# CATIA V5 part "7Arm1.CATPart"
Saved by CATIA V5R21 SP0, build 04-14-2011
Part number: Arm1
Bounding box of the stored display mesh (mm): x -25 to 11, y 73.29 to 108.29, z 135.805 to 383.286
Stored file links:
  C:\Users\水心\Desktop\Arm_Detailed_Design_Assembly_Manu\7Arm1.CATPart
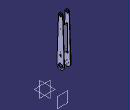
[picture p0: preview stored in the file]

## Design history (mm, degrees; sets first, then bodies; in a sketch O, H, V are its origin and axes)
Body1 (main body)
  DatumSurface1
  DatumSurface2
  Sketch1 on face of DatumSurface1, origin (-22, 0, 0), H (0, -1, 0), V (0, 0, 1)
    arc A1 centre (-90.79, 153.3046) radius 17.5 from (-108.2798, 153.9012) to (-73.3002, 153.9012) ccw
    point P1 (-90.79, 153.3046)
    arc A2 centre (-90.79, 373.3046) radius 10 from (-80.7958, 373.6456) to (-100.7842, 373.6456) ccw
    point P2 (-90.79, 373.3046)
    line L1 (-80.7958, 373.6456) -> (-73.3002, 153.9012)
    line L2 (-100.7842, 373.6456) -> (-108.2798, 153.9012)
    axis line L3 (-90.79, 373.3046) -> (-90.79, 153.3046)
    construction circle A3 centre (-90.79, 153.3046) radius 12.25
    circle A4 centre (-90.79, 161.8046) radius 1.25
    point P7 (-90.79, 161.8046)
    circle A5 centre (-90.79, 313.3046) radius 1.25
    point P8 (-90.79, 313.3046)
    circle A6 centre (-90.79, 213.3046) radius 1.25
    point P9 (-90.79, 213.3046)
    circle A7 centre (-90.79, 373.3046) radius 6.9
    circle A8 centre (-99.29, 153.3046) radius 1.25
    circle A9 centre (-90.79, 144.8046) radius 1.25
    circle A10 centre (-82.29, 153.3046) radius 1.25
    line L4 (-94.79, 203.3046) -> (-86.79, 203.3046)
    line L5 (-86.79, 203.3046) -> (-86.79, 193.3046)
    line L6 (-86.79, 193.3046) -> (-94.79, 193.3046)
    line L7 (-94.79, 193.3046) -> (-94.79, 203.3046)
    reference projected line E1 (-86.79, 203.3046) -> (-94.79, 203.3046) from edge [end face of Pad2 | face of Pocket3 from Sketch5.L1]
    reference projected line E2 (-86.79, 203.3046) -> (-86.79, 193.3046) from edge [face of Pocket3 from Sketch5.L4 | end face of Pad2]
    reference projected line E3 (-94.79, 193.3046) -> (-86.79, 193.3046) from edge [end face of Pad2 | face of Pocket3 from Sketch5.L3]
    reference projected line E4 (-94.79, 193.3046) -> (-94.79, 203.3046) from edge [face of Pocket3 from Sketch5.L2 | end face of Pad2]
    radius A1 = 17.5
    radius A2 = 10
    distance P2 P1 = 220
    radius A3 = 12.25
    radius A4 = 1.25
    distance P7 P1 = 8.5
    radius A5 = 1.25
    distance P8 P2 = 60
    radius A6 = 1.25
    distance P9 P8 = 100
    radius A7 = 6.9
    tangency: L1 A2, L1 A1, L2 A2, L2 A1
    vertical: L3 V, L5 V, L7 V
    coincidence: P7 L3, P8 L3, P9 L3, L4 E1, L5 E2, L6 E3, L7 E4
    horizontal: L4 H, L6 H
  Pad1: profile Sketch1, direction (-1, 0, 0), length 3
  Plane1: type Offset, RefPlane zx-plane, Offset 90
  Sketch2 on Plane1, origin (0, 90, 0), H (-1, 0, 0), V (0, 0, 1)
    circle A1 centre (23.5, 373.6456) radius 0.75
    point P1 (23.5, 373.6456)
    reference projected line E1 (22, 383.3046) -> (22, 373.6456) from edge [start face of Pad1 | face of Pad1 from Sketch1.A2]
    reference projected line E2 (22, 373.6456) -> (25, 373.6456) from edge [face of Pad1 from Sketch1.L2 | face of Pad1 from Sketch1.A2]
    radius A1 = 0.75
    distance P1 E1 = 1.5
    coincidence: P1 E2
  Pocket1: profile Sketch2, direction (0, -1, 0), length 20, mirrored extent
Body2
  DatumSurface3
  DatumCurve1
  DatumSurface4 to DatumSurface6
  Sketch3 on DatumSurface6, origin (11, 0, 0), H (0, -1, 0), V (0, 0, 1)
    arc A1 centre (-90.79, 153.3046) radius 17.5 from (-108.2798, 153.9012) to (-73.3002, 153.9012) ccw
    point P1 (-90.79, 153.3046)
    arc A2 centre (-90.79, 373.3046) radius 10 from (-80.7958, 373.6456) to (-100.7842, 373.6456) ccw
    point P2 (-90.79, 373.3046)
    axis line L1 (-90.79, 431.4654) -> (-90.79, 58.352)
    line L2 (-100.7842, 373.6456) -> (-108.2798, 153.9012)
    line L3 (-80.7958, 373.6456) -> (-73.3002, 153.9012)
    reference projected arc E1 centre (-90.79, 153.3046) radius 26.8116 from (-70.2512, 136.0705) to (-111.3288, 170.5388) ccw from edge of DatumCurve1
    circle A3 centre (-90.79, 153.3046) radius 10.4
    circle A4 centre (-90.79, 313.3046) radius 1.25
    point P9 (-90.79, 313.3046)
    circle A5 centre (-90.79, 213.3046) radius 1.25
    point P10 (-90.79, 213.3046)
    point P11 (-90.79, 228.3046)
    point P12 (-90.79, 303.3046)
    circle A6 centre (-90.79, 373.3046) radius 6.9
    radius A1 = 17.5
    radius A2 = 10
    distance P1 P2 = 220
    radius A3 = 10.4
    distance P9 P2 = 60
    distance P9 P10 = 100
    radius A4 = 1.25
    radius A5 = 1.25
    radius A6 = 6.9
    vertical: L1 V
    coincidence: P2 L1, P1 L1, P9 L1, P10 L1, L1 P11, L1 P12
    tangency: L2 A1, L2 A2, L3 A2, L3 A1
    concentricity: A1 E1
  Pad2: profile Sketch3, direction (-1, 0, 0), length 3
  Sketch4 on Plane1, origin (0, 90, 0), H (-1, 0, 0), V (0, 0, 1)
    circle A1 centre (-9.5, 373.6456) radius 0.75
    point P1 (-9.5, 373.6456)
    circle A2 centre (-9.5, 153.9012) radius 0.75
    point P2 (-9.5, 153.9012)
    reference projected line E1 (-8, 163.7046) -> (-8, 142.9046) from edge [end face of Pad2 | face of Pad2 from Sketch3.A3]
    reference projected line E2 (-8, 383.3046) -> (-8, 373.6456) from edge [face of Pad2 from Sketch3.A2 | end face of Pad2]
    reference projected line E3 (-11, 373.6456) -> (-8, 373.6456) from edge [face of Pad2 from Sketch3.L2 | face of Pad2 from Sketch3.A2]
    reference projected line E4 (-11, 153.9012) -> (-8, 153.9012) from edge [face of Pad2 from Sketch3.A1 | face of Pad2 from Sketch3.L2]
    radius A2 = 0.75
    distance P2 E1 = 1.5
    radius A1 = 0.75
    distance P1 E2 = 1.5
    coincidence: P1 E3, E4 P2
  Pocket2: profile Sketch4, direction (0, -1, 0), length 20, mirrored extent
  Plane2: stored without definition
  Plane3: stored without definition
  DatumSurface7
  Sketch5 on start face of Pad2, origin (11, 0, 0), H (0, 1, 0), V (0, 0, 1)
    line L1 (86.79, 203.3046) -> (94.79, 203.3046)
    line L2 (94.79, 203.3046) -> (94.79, 193.3046)
    line L3 (94.79, 193.3046) -> (86.79, 193.3046)
    line L4 (86.79, 193.3046) -> (86.79, 203.3046)
    reference intersected line E1 through (90.79, 0) direction (0, -1) from Plane2
    reference intersected line E2 through (0, 153.3046) direction (1, 0) from Plane3
    distance L2 E1 = 4
    length L1 = 8
    length L2 = 10
    distance L3 E2 = 40
    horizontal: L1 H, L3 H
    vertical: L2 V, L4 V
  Pocket3: profile Sketch5, direction (-1, 0, 0), through (limit type 3)
Body3
  Sketch6 on end face of Pad2, origin (8, 0, 0), H (0, -1, 0), V (0, 0, 1)
    line L1 (-92.79, 323.3046) -> (-88.79, 323.3046)
    line L2 (-88.79, 323.3046) -> (-88.79, 203.3046)
    line L3 (-88.79, 203.3046) -> (-92.79, 203.3046)
    line L4 (-92.79, 203.3046) -> (-92.79, 323.3046)
    reference projected circle E1 centre (-90.79, 213.3046) radius 1.25 from edge [end face of Pad1 | face of Pad1 from Sketch1.A6]
    reference projected circle E2 centre (-90.79, 213.3046) radius 1.25 from edge [end face of Pad1 | face of Pad1 from Sketch1.A6]
    length L1 = 4
    length L2 = 120
    distance L2 E1 = 0.75
    distance L3 E2 = 8.75
    horizontal: L1 H, L3 H
    vertical: L2 V, L4 V
  Pad3: profile Sketch6, direction (-1, 0, 0), up to start face of Pad1
  Sketch7 on end face of Pad3, origin (-22, 0, 0), H (0, -1, 0), V (0, 0, 1)
    circle A1 centre (-90.79, 313.3046) radius 1.25
    point P1 (-90.79, 313.3046)
    circle A2 centre (-90.79, 213.3046) radius 1.25
    point P2 (-90.79, 213.3046)
    reference projected line E1 (-88.79, 203.3046) -> (-88.79, 323.3046) from edge [face of Pad3 from Sketch6.L2 | end face of Pad3]
    reference projected line E2 (-88.79, 203.3046) -> (-88.79, 323.3046) from edge [face of Pad3 from Sketch6.L2 | end face of Pad3]
    reference projected line E3 (-92.79, 323.3046) -> (-88.79, 323.3046) from edge [end face of Pad3 | face of Pad3 from Sketch6.L1]
    reference projected line E4 (-88.79, 203.3046) -> (-92.79, 203.3046) from edge [end face of Pad3 | face of Pad3 from Sketch6.L3]
    radius A2 = 1.25
    distance P2 E1 = 2
    radius A1 = 1.25
    distance P1 E2 = 2
    distance P1 E3 = 10
    distance P2 E4 = 10
  Pocket4: profile Sketch7, direction (1, 0, 0), length 5
  Sketch8 on start face of Pad3, origin (8, 0, 0), H (0, 1, 0), V (0, 0, 1)
    circle A1 centre (90.79, 313.3046) radius 1.25
    point P1 (90.79, 313.3046)
    circle A2 centre (90.79, 213.3046) radius 1.25
    point P2 (90.79, 213.3046)
    reference projected line E1 (88.79, 203.3046) -> (88.79, 323.3046) from edge [start face of Pad3 | face of Pad3 from Sketch6.L2]
    reference projected line E2 (92.79, 203.3046) -> (88.79, 203.3046) from edge [start face of Pad3 | face of Pad3 from Sketch6.L3]
    reference projected line E3 (88.79, 323.3046) -> (92.79, 323.3046) from edge [start face of Pad3 | face of Pad3 from Sketch6.L1]
    reference projected line E4 (88.79, 203.3046) -> (88.79, 323.3046) from edge [start face of Pad3 | face of Pad3 from Sketch6.L2]
    distance P2 E1 = 2
    radius A2 = 1.25
    distance P2 E2 = 10
    radius A1 = 1.25
    distance P1 E3 = 10
    distance P1 E4 = 2
  Pocket5: profile Sketch8, direction (-1, 0, 0), length 5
